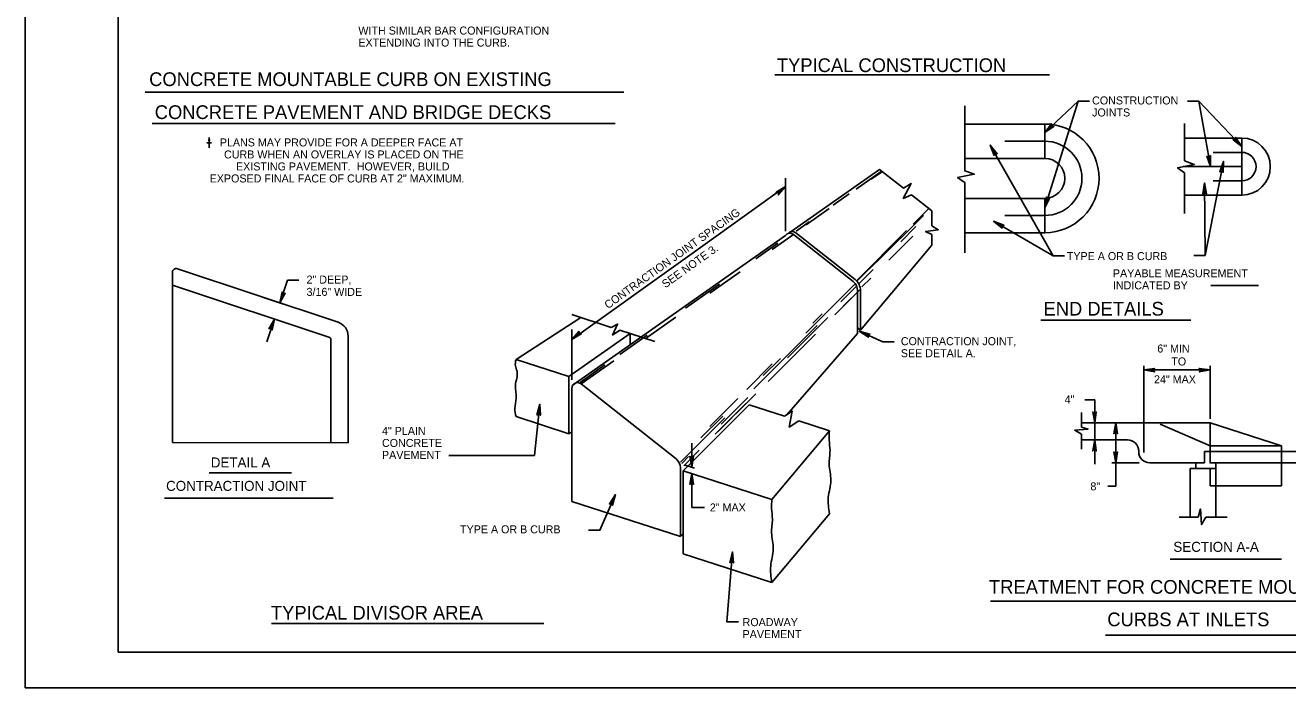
# Model space of a CAD drawing. Extents: x 638443 to 639347, y 298415 to 299009.
# Drawn here: x 638443 to 638973, y 298415 to 298693 of the extents above; entities that cross this region are included whole.
import ezdxf

# ---------------------------------------------------------------- set-up
doc = ezdxf.new("R2010")
doc.units = 0
for name, color, linetype in [('1', 7, 'Continuous'), ('2', 7, 'Continuous'), ('3', 7, 'Continuous'), ('PLT-BNDY', 7, 'Continuous')]:
    doc.layers.add(name, color=color, linetype=linetype)

msp = doc.modelspace()

# ---------------------------------------------------------------- linework, layer by layer
at = {"layer": '1'}
for p, q in [((638482.08, 298993.73), (638482.08, 298429.73)), ((638482.08, 298429.73), (639268.08, 298429.73))]:
    msp.add_line(p, q, dxfattribs=at)
at = {"layer": '2'}
for p, q in [((638885.14, 298661), (638871.16, 298647.75)), ((638871.16, 298616.15), (638885.14, 298661)), ((638889.94, 298661), (638885.14, 298661)), ((638931.09, 298661), (638935.89, 298661)), ((638935.89, 298661), (638953.86, 298641.89)), ((638940.78, 298633.45), (638935.89, 298661)), ((638837.56, 298658.96), (638837.56, 298631.86)), ((638871.16, 298651.34), (638837.56, 298651.34)), ((638871.16, 298651.34), (638871.16, 298636.94)), ((638929.86, 298651.51), (638929.86, 298635.89)), ((638953.86, 298645.45), (638929.86, 298645.45)), ((638953.86, 298645.45), (638953.86, 298621.45)), ((638874.69, 298596.02), (638848.27, 298642.53)), ((638871.16, 298644.14), (638854.36, 298644.14)), ((638871.16, 298636.94), (638837.56, 298636.94)), ((638938.57, 298596.15), (638946.25, 298635.65)), ((638953.86, 298639.45), (638941.86, 298639.45)), ((638764.61, 298606.21), (638801.76, 298632.32)), ((638791.96, 298624.06), (638802.41, 298631.4)), ((638798.26, 298628.17), (638802.56, 298631.19)), ((638801.76, 298632.32), (638811.82, 298624.38)), ((638953.86, 298633.45), (638929.25, 298633.45)), ((638929.86, 298630.92), (638929.86, 298613.79)), ((638762.3, 298625.08), (638722.12, 298596.35)), ((638762.3, 298628.55), (638762.3, 298606.4)), ((638837.56, 298626.63), (638837.56, 298597.32)), ((638938.57, 298596.15), (638938.23, 298626.6)), ((638953.86, 298627.45), (638941.86, 298627.45)), ((638782.32, 298617.28), (638789.04, 298622)), ((638815.26, 298621.66), (638823.76, 298614.95)), ((638871.16, 298620.14), (638837.56, 298620.14)), ((638871.16, 298620.14), (638871.16, 298605.74)), ((638953.86, 298621.45), (638929.86, 298621.45)), ((638770.94, 298608.97), (638780.69, 298615.82)), ((638815.83, 298609.3), (638822.62, 298616.09)), ((638823.76, 298608.61), (638823.76, 298614.95)), ((638766.76, 298606.35), (638772.27, 298610.22)), ((638800.53, 298593.32), (638820.19, 298612.99)), ((638810.71, 298601.91), (638817.08, 298608.28)), ((638874.69, 298596.02), (638849.67, 298610.55)), ((638871.16, 298612.94), (638854.36, 298612.94)), ((638673.07, 298541.89), (638762.3, 298604.59)), ((638756.64, 298598.64), (638765.67, 298604.98)), ((638765.67, 298604.98), (638790.73, 298585.2)), ((638766.68, 298605.71), (638791.48, 298586.14)), ((638791.94, 298585.41), (638813.15, 298606.62)), ((638805.67, 298594.22), (638815.72, 298604.27)), ((638807.9, 298600.92), (638811.14, 298604.16)), ((638823.76, 298600.55), (638823.76, 298604.94)), ((638871.16, 298605.74), (638837.56, 298605.74)), ((638749.88, 298594.82), (638759.07, 298601.27)), ((638793.76, 298564.78), (638823.76, 298600.55)), ((638722.12, 298596.35), (638672.56, 298560.89)), ((638792.16, 298585.18), (638802.54, 298595.56)), ((638879.49, 298596.02), (638874.69, 298596.02)), ((638933.77, 298596.15), (638938.57, 298596.15)), ((638504.92, 298589.16), (638504.92, 298517.73)), ((638574.45, 298568.12), (638506.95, 298590.62)), ((638730.55, 298580.31), (638743.27, 298589.24)), ((638793.07, 298584.27), (638799.09, 298590.29)), ((638794.4, 298582.95), (638798.07, 298586.62)), ((638570.96, 298561.69), (638504.92, 298583.7)), ((638549.98, 298576.27), (638553.17, 298585.84)), ((638553.17, 298585.84), (638557.97, 298585.84)), ((638720.28, 298574.02), (638734.63, 298584.1)), ((638770.81, 298563.61), (638791.22, 298584.01)), ((638783.66, 298571.99), (638793.45, 298581.78)), ((638785.57, 298576.77), (638792.02, 298583.21)), ((638792.56, 298563.35), (638792.56, 298581.43)), ((638793.76, 298564.78), (638793.76, 298581.43)), ((638960.92, 298583.51), (638940.83, 298583.51)), ((638542.29, 298578.84), (638551.57, 298575.74)), ((638782.99, 298571.31), (638789.91, 298578.24)), ((638689.15, 298565.95), (638672.51, 298571.35)), ((638773.83, 298567.74), (638777.74, 298571.65)), ((638544.51, 298559.88), (638547.7, 298569.44)), ((638649.16, 298552.55), (638676.3, 298570.12)), ((638703.39, 298561.22), (638716.31, 298570.3)), ((638749.04, 298540.24), (638775.63, 298566.83)), ((638763.1, 298553.22), (638780.08, 298570.2)), ((638792.56, 298565.73), (638793.76, 298564.78)), ((638571.45, 298517.58), (638571.45, 298561.01)), ((638578.65, 298517.57), (638578.65, 298562.29)), ((638671.36, 298545.35), (638697.03, 298563.4)), ((638672.56, 298544.03), (638672.56, 298565.16)), ((638692.68, 298554.62), (638704.25, 298562.76)), ((638707.4, 298560.03), (638692.76, 298564.78)), ((638697.03, 298563.4), (638697.03, 298558.73)), ((638754.95, 298543.27), (638774.83, 298563.16)), ((638762.86, 298529.34), (638792.56, 298563.35)), ((638671.36, 298545.35), (638649.16, 298552.55)), ((638676.01, 298542.91), (638686.41, 298550.22)), ((638676.44, 298542.29), (638690.23, 298551.97)), ((638746.01, 298539.92), (638756.73, 298550.65)), ((638752.93, 298545.73), (638760.2, 298552.99)), ((638912.74, 298513.5), (638912.74, 298549.83)), ((638940.58, 298527.6), (638940.58, 298549.83)), ((638671.36, 298521.35), (638671.36, 298545.35)), ((638912.74, 298548.15), (638940.58, 298548.15)), ((638672.56, 298492.86), (638672.56, 298540.4)), ((638676.44, 298542.29), (638716.33, 298510.8)), ((638730.48, 298524.39), (638742.21, 298536.12)), ((638732.83, 298521.15), (638749.78, 298538.11)), ((638733.83, 298522.16), (638745.67, 298534)), ((638735.28, 298525.4), (638746.45, 298536.57)), ((638892.15, 298535.62), (638887.91, 298535.62)), ((638892.15, 298525.92), (638892.15, 298535.62)), ((638671.36, 298521.35), (638649.16, 298528.55)), ((638719.36, 298505.75), (638747.06, 298533.45)), ((638726.79, 298519.59), (638735.95, 298528.75)), ((638747.06, 298533.45), (638761.89, 298528.67)), ((638886.58, 298530.3), (638886.58, 298524.07)), ((638718.16, 298509.35), (638736.87, 298528.06)), ((638767.91, 298526.73), (638780.75, 298522.59)), ((638940.58, 298525.92), (638886.58, 298525.92)), ((638888.26, 298525.92), (638902.72, 298525.92)), ((638888.26, 298525.92), (638893.83, 298525.92)), ((638892.15, 298508.64), (638892.15, 298525.92)), ((638901.04, 298525.92), (638901.04, 298499.32)), ((638919.54, 298525.3), (638940.58, 298516.32)), ((638940.58, 298513.92), (638940.58, 298525.92)), ((638940.58, 298525.92), (638970.58, 298516.32)), ((638504.92, 298517.73), (638578.65, 298517.57)), ((638671.36, 298521.35), (638672.56, 298522.2)), ((638671.36, 298521.35), (638671.36, 298521.35)), ((638756.56, 298493.75), (638780.75, 298522.59)), ((638886.58, 298521.1), (638886.58, 298514.86)), ((638905.9, 298518.72), (638886.58, 298518.72)), ((638888.26, 298518.72), (638893.83, 298518.72)), ((638719.59, 298507.92), (638726.08, 298514.41)), ((638723, 298507.3), (638723, 298517.38)), ((638910.58, 298513.8), (638910.58, 298514.04)), ((638940.58, 298513.92), (638938.18, 298513.92)), ((638938.18, 298513.92), (638938.18, 298509.12)), ((638970.58, 298516.32), (638940.58, 298516.32)), ((638970.58, 298513.93), (638970.58, 298516.32)), ((638970.58, 298499.52), (638970.58, 298513.93)), ((638718.7, 298508.81), (638721.62, 298511.74)), ((638719.59, 298507.92), (638723.66, 298511.99)), ((638720.13, 298508.16), (638724.02, 298506.9)), ((638910.73, 298509.12), (638899.36, 298509.12)), ((638934.58, 298509.12), (638915.26, 298509.12)), ((638938.18, 298509.12), (638934.58, 298509.12)), ((638934.58, 298509.12), (638934.58, 298506.72)), ((638942.98, 298506.72), (638942.98, 298509.12)), ((638942.98, 298509.12), (638942.98, 298486.32)), ((638718.16, 298507.03), (638718.16, 298478.15)), ((638719.36, 298505.75), (638756.56, 298493.75)), ((638719.36, 298470.95), (638719.36, 298505.75)), ((638932.18, 298506.72), (638942.98, 298506.72)), ((638932.18, 298506.72), (638932.18, 298486.32)), ((638940.58, 298506.72), (638940.58, 298499.52)), ((638901.04, 298499.32), (638897.63, 298499.32)), ((638940.58, 298499.52), (638970.58, 298499.52)), ((638718.16, 298478.15), (638672.56, 298492.86)), ((638756.56, 298458.95), (638780.75, 298487.79)), ((638718.16, 298478.15), (638719.36, 298479.53)), ((638719.36, 298470.95), (638719.36, 298470.95)), ((638719.36, 298470.95), (638756.56, 298458.95))]:
    msp.add_line(p, q, dxfattribs=at)
for points in [[(638874.7, 298650.36), (638874.36, 298650.47), (638871.16, 298647.75), (638874.7, 298650.36), (638874.99, 298650.37), (638871.16, 298647.75), (638874.06, 298650.79), (638873.95, 298651.12), (638871.16, 298647.75), (638873.98, 298651.43), (638873.95, 298651.12)], [(638951.27, 298645.44), (638951.15, 298645.11), (638953.86, 298641.89), (638951.27, 298645.44), (638951.26, 298645.74), (638953.86, 298641.89), (638950.84, 298644.81), (638950.5, 298644.7), (638953.86, 298641.89), (638950.19, 298644.73), (638950.5, 298644.7)], [(638849.95, 298638.47), (638850.14, 298638.77), (638848.27, 298642.53), (638849.95, 298638.47), (638849.89, 298638.18), (638848.27, 298642.53), (638850.52, 298638.99), (638850.87, 298639.01), (638848.27, 298642.53), (638851.17, 298638.9), (638850.87, 298639.01)], [(638929.86, 298635.89), (638933.9, 298634.4), (638926.93, 298632.97), (638929.86, 298630.92)], [(638940.55, 298637.84), (638940.27, 298637.62), (638940.78, 298633.45), (638940.55, 298637.84), (638940.7, 298638.09), (638940.78, 298633.45), (638939.84, 298637.54), (638939.51, 298637.64), (638940.78, 298633.45), (638939.26, 298637.83), (638939.51, 298637.64)], [(638944.88, 298631.47), (638945.23, 298631.57), (638946.25, 298635.65), (638944.88, 298631.47), (638944.65, 298631.29), (638946.25, 298635.65), (638945.66, 298631.49), (638945.93, 298631.28), (638946.25, 298635.65), (638946.09, 298631.01), (638945.93, 298631.28)], [(638837.25, 298631.86), (638841.53, 298630.28), (638834.56, 298628.85), (638837.73, 298626.63)], [(638759.29, 298621.87), (638759.22, 298622.22), (638762.3, 298625.08), (638759.29, 298621.87), (638759.24, 298621.58), (638762.3, 298625.08), (638758.94, 298622.56), (638758.62, 298622.7), (638762.3, 298625.08), (638758.31, 298622.71), (638758.62, 298622.7)], [(638811.82, 298624.38), (638815.05, 298626.39), (638811.7, 298620.14), (638815.26, 298621.66)], [(638937.73, 298622.24), (638938.04, 298622.4), (638938.23, 298626.6), (638937.73, 298622.24), (638937.54, 298622.01), (638938.23, 298626.6), (638938.48, 298622.41), (638938.8, 298622.26), (638938.23, 298626.6), (638939.01, 298622.03), (638938.8, 298622.26)], [(638872.98, 298620.15), (638872.63, 298620.09), (638871.16, 298616.15), (638872.98, 298620.15), (638873.23, 298620.31), (638871.16, 298616.15), (638872.21, 298620.22), (638871.95, 298620.46), (638871.16, 298616.15), (638871.83, 298620.75), (638871.95, 298620.46)], [(638823.76, 298608.61), (638826.44, 298606.95), (638821.08, 298606.28), (638823.76, 298604.94)], [(638853.17, 298607.89), (638853.19, 298608.24), (638849.67, 298610.55), (638853.17, 298607.89), (638853.26, 298607.61), (638849.67, 298610.55), (638853.4, 298608.62), (638853.69, 298608.81), (638849.67, 298610.55), (638854, 298608.88), (638853.69, 298608.81)], [(638550.99, 298580.55), (638551.23, 298580.29), (638549.98, 298576.27), (638550.99, 298580.55), (638550.89, 298580.83), (638549.98, 298576.27), (638551.64, 298580.13), (638551.99, 298580.16), (638549.98, 298576.27), (638552.27, 298580.31), (638551.99, 298580.16)], [(638546.69, 298565.17), (638546.45, 298565.43), (638547.7, 298569.44), (638546.69, 298565.17), (638546.79, 298564.89), (638547.7, 298569.44), (638546.04, 298565.59), (638545.69, 298565.56), (638547.7, 298569.44), (638545.41, 298565.41), (638545.69, 298565.56)], [(638689.15, 298565.95), (638691.76, 298567.36), (638689.68, 298562.73), (638692.76, 298564.78)], [(638675.56, 298564.1), (638675.64, 298563.75), (638672.56, 298560.89), (638675.56, 298564.1), (638675.61, 298564.39), (638672.56, 298560.89), (638675.92, 298563.41), (638676.23, 298563.27), (638672.56, 298560.89), (638676.55, 298563.26), (638676.23, 298563.27)], [(638807.94, 298559.97), (638803.14, 298559.97), (638793.23, 298564.39)], [(638796.99, 298562.11), (638796.97, 298562.47), (638793.23, 298564.39), (638796.99, 298562.11), (638797.12, 298561.85), (638793.23, 298564.39), (638797.14, 298562.87), (638797.41, 298563.09), (638793.23, 298564.39), (638797.71, 298563.19), (638797.41, 298563.09)], [(638917.08, 298547.49), (638916.93, 298547.81), (638912.74, 298548.15), (638917.08, 298547.49), (638917.3, 298547.3), (638912.74, 298548.15), (638916.94, 298548.25), (638917.1, 298548.56), (638912.74, 298548.15), (638917.34, 298548.77), (638917.1, 298548.56)], [(638936.24, 298547.49), (638936.39, 298547.81), (638940.58, 298548.15), (638936.24, 298547.49), (638936.02, 298547.3), (638940.58, 298548.15), (638936.38, 298548.25), (638936.23, 298548.56), (638940.58, 298548.15), (638935.98, 298548.77), (638936.23, 298548.56)], [(638656.88, 298512.15), (638659.17, 298533.75)], [(638658.17, 298529.47), (638658.5, 298529.6), (638659.17, 298533.75), (638658.17, 298529.47), (638657.95, 298529.27), (638659.17, 298533.75), (638658.93, 298529.56), (638659.23, 298529.37), (638659.17, 298533.75), (638659.41, 298529.12), (638659.23, 298529.37)], [(638761.89, 298528.67), (638765.06, 298530.86), (638763.9, 298524.15), (638767.91, 298526.73)], [(638891.49, 298530.27), (638891.81, 298530.11), (638892.15, 298525.92), (638891.49, 298530.27), (638891.3, 298530.49), (638892.15, 298525.92), (638892.25, 298530.12), (638892.56, 298530.28), (638892.15, 298525.92), (638892.76, 298530.52), (638892.56, 298530.28)], [(638886.58, 298524.07), (638889.34, 298523.28), (638883.73, 298522.82), (638886.58, 298521.1)], [(638900.38, 298521.58), (638900.7, 298521.74), (638901.04, 298525.92), (638900.38, 298521.58), (638900.19, 298521.36), (638901.04, 298525.92), (638901.14, 298521.73), (638901.45, 298521.57), (638901.04, 298525.92), (638901.65, 298521.33), (638901.45, 298521.57)], [(638891.49, 298514.38), (638891.81, 298514.54), (638892.15, 298518.72), (638891.49, 298514.38), (638891.3, 298514.16), (638892.15, 298518.72), (638892.25, 298514.53), (638892.56, 298514.37), (638892.15, 298518.72), (638892.76, 298514.13), (638892.56, 298514.37)], [(638900.38, 298513.47), (638900.7, 298513.31), (638901.04, 298509.12), (638900.38, 298513.47), (638900.19, 298513.69), (638901.04, 298509.12), (638901.14, 298513.32), (638901.45, 298513.48), (638901.04, 298509.12), (638901.65, 298513.72), (638901.45, 298513.48)], [(638620.9, 298512.15), (638656.88, 298512.15)], [(638722.34, 298511.64), (638722.66, 298511.49), (638723, 298507.3), (638722.34, 298511.64), (638722.14, 298511.86), (638723, 298507.3), (638723.1, 298511.49), (638723.41, 298511.65), (638723, 298507.3), (638723.61, 298511.9), (638723.41, 298511.65)], [(638722.34, 298500.3), (638722.66, 298500.46), (638723, 298504.64), (638722.34, 298500.3), (638722.14, 298500.08), (638723, 298504.64), (638723.1, 298500.45), (638723.41, 298500.29), (638723, 298504.64), (638723.61, 298500.05), (638723.41, 298500.29)], [(638723, 298504.64), (638723, 298490.33)], [(638679.58, 298480.86), (638684.38, 298480.86), (638690.86, 298495.81)], [(638688.62, 298492.02), (638688.98, 298492.05), (638690.86, 298495.81), (638688.62, 298492.02), (638688.36, 298491.89), (638690.86, 298495.81), (638689.38, 298491.87), (638689.61, 298491.61), (638690.86, 298495.81), (638689.7, 298491.31), (638689.61, 298491.61)], [(638723, 298490.33), (638728.3, 298490.33)], [(638927.64, 298486.32), (638935.54, 298486.32)], [(638935.54, 298486.32), (638936.53, 298489.79), (638937, 298483.24), (638938.76, 298486.32)], [(638938.76, 298486.32), (638947.76, 298486.32)], [(638742.5, 298442.33), (638737.7, 298442.33), (638740.05, 298471.74)], [(638739.15, 298467.44), (638739.48, 298467.58), (638740.05, 298471.74), (638739.15, 298467.44), (638738.95, 298467.23), (638740.05, 298471.74), (638739.92, 298467.55), (638740.22, 298467.37), (638740.05, 298471.74), (638740.41, 298467.12), (638740.22, 298467.37)]]:
    msp.add_lwpolyline(points, dxfattribs=at)
msp.add_lwpolyline([(638940.58, 298513.92), (638940.58, 298509.12), (638993.38, 298509.12), (638993.38, 298513.92)], close=True, dxfattribs=at)
for centre, radius, start, end in [((638871.16, 298628.54), 22.8, 270, 90), ((638953.86, 298633.45), 12, 270, 90), ((638871.16, 298628.54), 15.6, 270, 90), ((638871.16, 298628.54), 8.4, 270, 90), ((638953.86, 298633.45), 6, 270, 90), ((638764.18, 298603.1), 2.4, 51.7096, 141.7081), ((638765.16, 298603.79), 2.4, 51.7096, 141.7081), ((638506.46, 298589.16), 1.54, 71.5649, 180), ((638787.76, 298581.43), 4.8, 0, 51.7098), ((638787.76, 298581.43), 6, 0, 51.7098), ((638572.51, 298562.29), 6.14, 0, 71.5651), ((638570.73, 298561.01), 0.72, 0, 71.5649), ((638674.96, 298540.4), 2.4, 51.7096, 180), ((638905.9, 298514.04), 4.68, 0, 90), ((638915.26, 298513.8), 4.68, 180, 270), ((638713.36, 298507.03), 4.8, 0, 51.7098)]:
    msp.add_arc(centre, radius, start, end, dxfattribs=at)
for points in [[(638649.16, 298552.55), (638648.86, 298549.78), (638649.58, 298547.62), (638648.86, 298541.66), (638649.22, 298536.25), (638648.68, 298531.91), (638649.16, 298528.55)], [(638780.75, 298522.59), (638780.63, 298518.81), (638780.99, 298514.3), (638780.63, 298508.52), (638781.35, 298501.84), (638780.27, 298494.62), (638780.75, 298487.79)], [(638756.56, 298493.75), (638756.44, 298489.98), (638756.8, 298485.46), (638756.44, 298479.69), (638757.16, 298473.01), (638756.08, 298465.79), (638756.56, 298458.95)]]:
    msp.add_spline(points, degree=3, dxfattribs=at)
at = {"layer": '3'}
for p, q in [((638757.87, 298672.03), (638873.12, 298672.03)), ((638493.41, 298664.76), (638694.48, 298664.76)), ((638496.41, 298651.54), (638690.82, 298651.54)), ((638520.31, 298645.69), (638520.31, 298641.3)), ((638520.31, 298645.69), (638520.31, 298643.5)), ((638519.39, 298643.5), (638520.31, 298643.5)), ((638519.83, 298644.59), (638520.31, 298644.59)), ((638520.31, 298644.59), (638520.79, 298644.59)), ((638520.31, 298643.5), (638521.23, 298643.5)), ((638869.49, 298569.06), (638932.52, 298569.06)), ((638520.33, 298504.93), (638554.94, 298504.93)), ((638501.54, 298494.24), (638572.38, 298494.24)), ((638923.83, 298468.67), (638970.53, 298468.67)), ((638848.33, 298451.1), (639030.74, 298451.1)), ((638546.44, 298441.76), (638660.77, 298441.76)), ((638896.68, 298436.84), (638982.5, 298436.84))]:
    msp.add_line(p, q, dxfattribs=at)
at = {"layer": 'PLT-BNDY'}
msp.add_lwpolyline([(638443.08, 299008.73), (639284.08, 299008.73), (639284.08, 298414.73), (638443.08, 298414.73)], close=True, dxfattribs=at)

# ---------------------------------------------------------------- texts
at = {"layer": '3'}
for s, height, p in [('WITH SIMILAR BAR CONFIGURATION ', 3.36, (638582.95, 298688.89)), ('EXTENDING INTO THE CURB.', 3.36, (638582.95, 298683.85)), ('TYPICAL CONSTRUCTION', 5.76, (638758.67, 298673.15)), ('CONCRETE MOUNTABLE CURB ON EXISTING', 5.76, (638495.11, 298667.28)), ('CONSTRUCTION', 3.36, (638891.03, 298659.56)), ('CONCRETE PAVEMENT AND BRIDGE DECKS', 5.76, (638497.45, 298653.44)), ('JOINTS', 3.36, (638891.03, 298654.52)), ('PLANS MAY PROVIDE FOR A DEEPER FACE AT', 3.36, (638524.78, 298641.94)), ('CURB WHEN AN OVERLAY IS PLACED ON THE', 3.36, (638526.54, 298636.9)), ('EXISTING PAVEMENT.  HOWEVER, BUILD', 3.36, (638531.57, 298631.86)), ('EXPOSED FINAL FACE OF CURB AT 2" MAXIMUM.', 3.36, (638520.51, 298626.82)), ('TYPE A OR B CURB', 3.36, (638880.42, 298594.22)), ('2" DEEP,', 3.36, (638561.2, 298584.37)), ('PAYABLE MEASUREMENT', 3.36, (638899.76, 298586.99)), ('3/16" WIDE', 3.36, (638561.2, 298579.21)), ('INDICATED BY', 3.36, (638899.76, 298581.95)), ('END DETAILS', 5.76, (638870.63, 298570.92)), ('CONTRACTION JOINT,', 3.36, (638810.73, 298558.51)), ('SEE DETAIL A.', 3.36, (638810.73, 298553.47)), ('6" MIN', 3.36, (638918.41, 298555.43)), ('TO', 3.36, (638924.28, 298550)), ('24" MAX', 3.36, (638917.02, 298542.5)), ('4"', 3.36, (638879.48, 298534.04)), ('4" PLAIN', 3.36, (638592.87, 298520.84)), ('CONCRETE', 3.36, (638592.87, 298515.8)), ('PAVEMENT', 3.36, (638592.87, 298510.76)), ('DETAIL A', 4.2, (638520.99, 298507.18)), ('CONTRACTION JOINT', 4.2, (638502.22, 298497.36)), ('8"', 3.36, (638890.32, 298497.56)), ('2" MAX', 3.36, (638730.53, 298488.73)), ('TYPE A OR B CURB', 3.36, (638625.64, 298479.54)), ('SECTION A-A', 4.2, (638925.14, 298471.77)), ('TREATMENT FOR CONCRETE MOUNTABLE', 5.76, (638847.75, 298454.18)), ('TYPICAL DIVISOR AREA', 5.76, (638546.24, 298443.32)), ('ROADWAY', 3.36, (638744.28, 298440.59)), ('CURBS AT INLETS', 5.76, (638897.42, 298440.54)), ('PAVEMENT', 3.36, (638744.28, 298435.55))]:
    msp.add_text(s, height=height, dxfattribs=at).set_placement(p)
for s, p in [('CONTRACTION JOINT SPACING', (638687.76, 298573.57)), ('SEE NOTE 3.', (638711.87, 298582.35))]:
    msp.add_text(s, height=3.36, rotation=35.5736, dxfattribs=at).set_placement(p)

doc.saveas('drawing.dxf')
